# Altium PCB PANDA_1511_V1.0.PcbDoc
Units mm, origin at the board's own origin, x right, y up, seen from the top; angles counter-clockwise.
Board outline 50 x 34 mm, 2 copper layers (Top Layer, Bottom Layer); 45 components, 50 nets, 138 pads, 65 vias.
Unrouted connection lines stored in the file: 1.
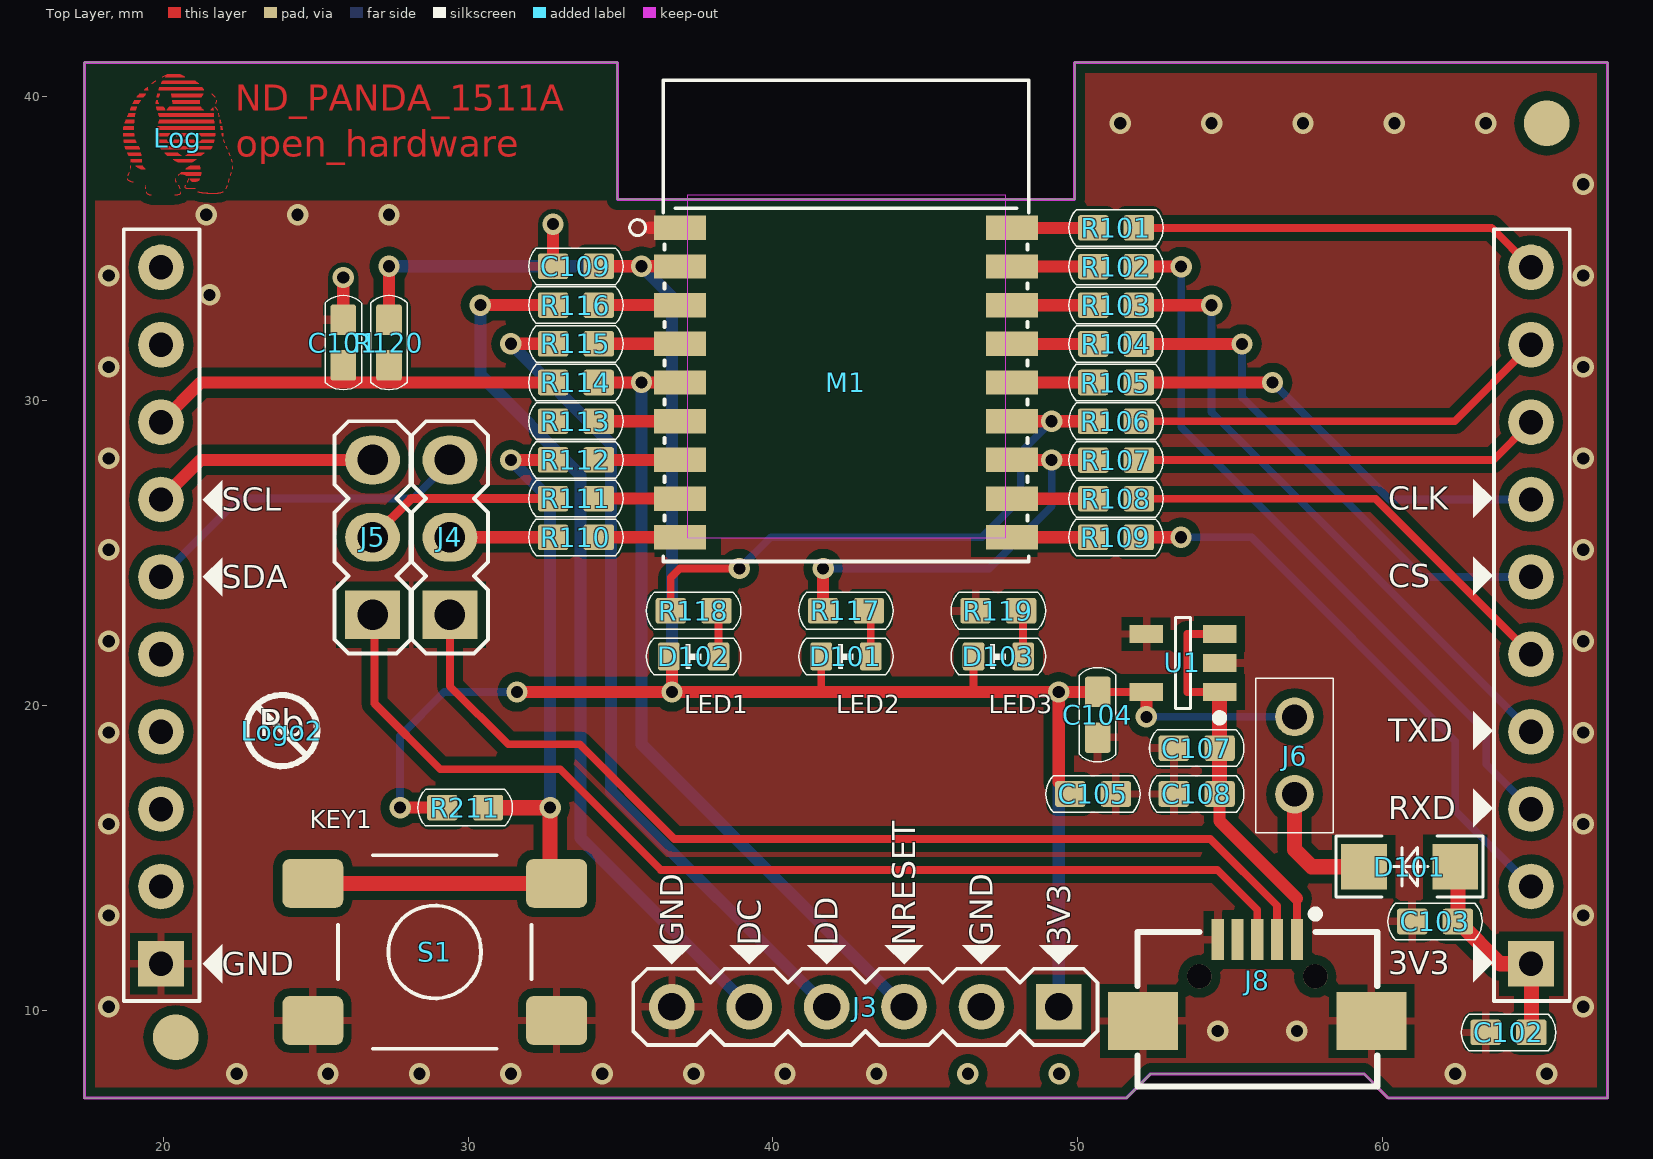
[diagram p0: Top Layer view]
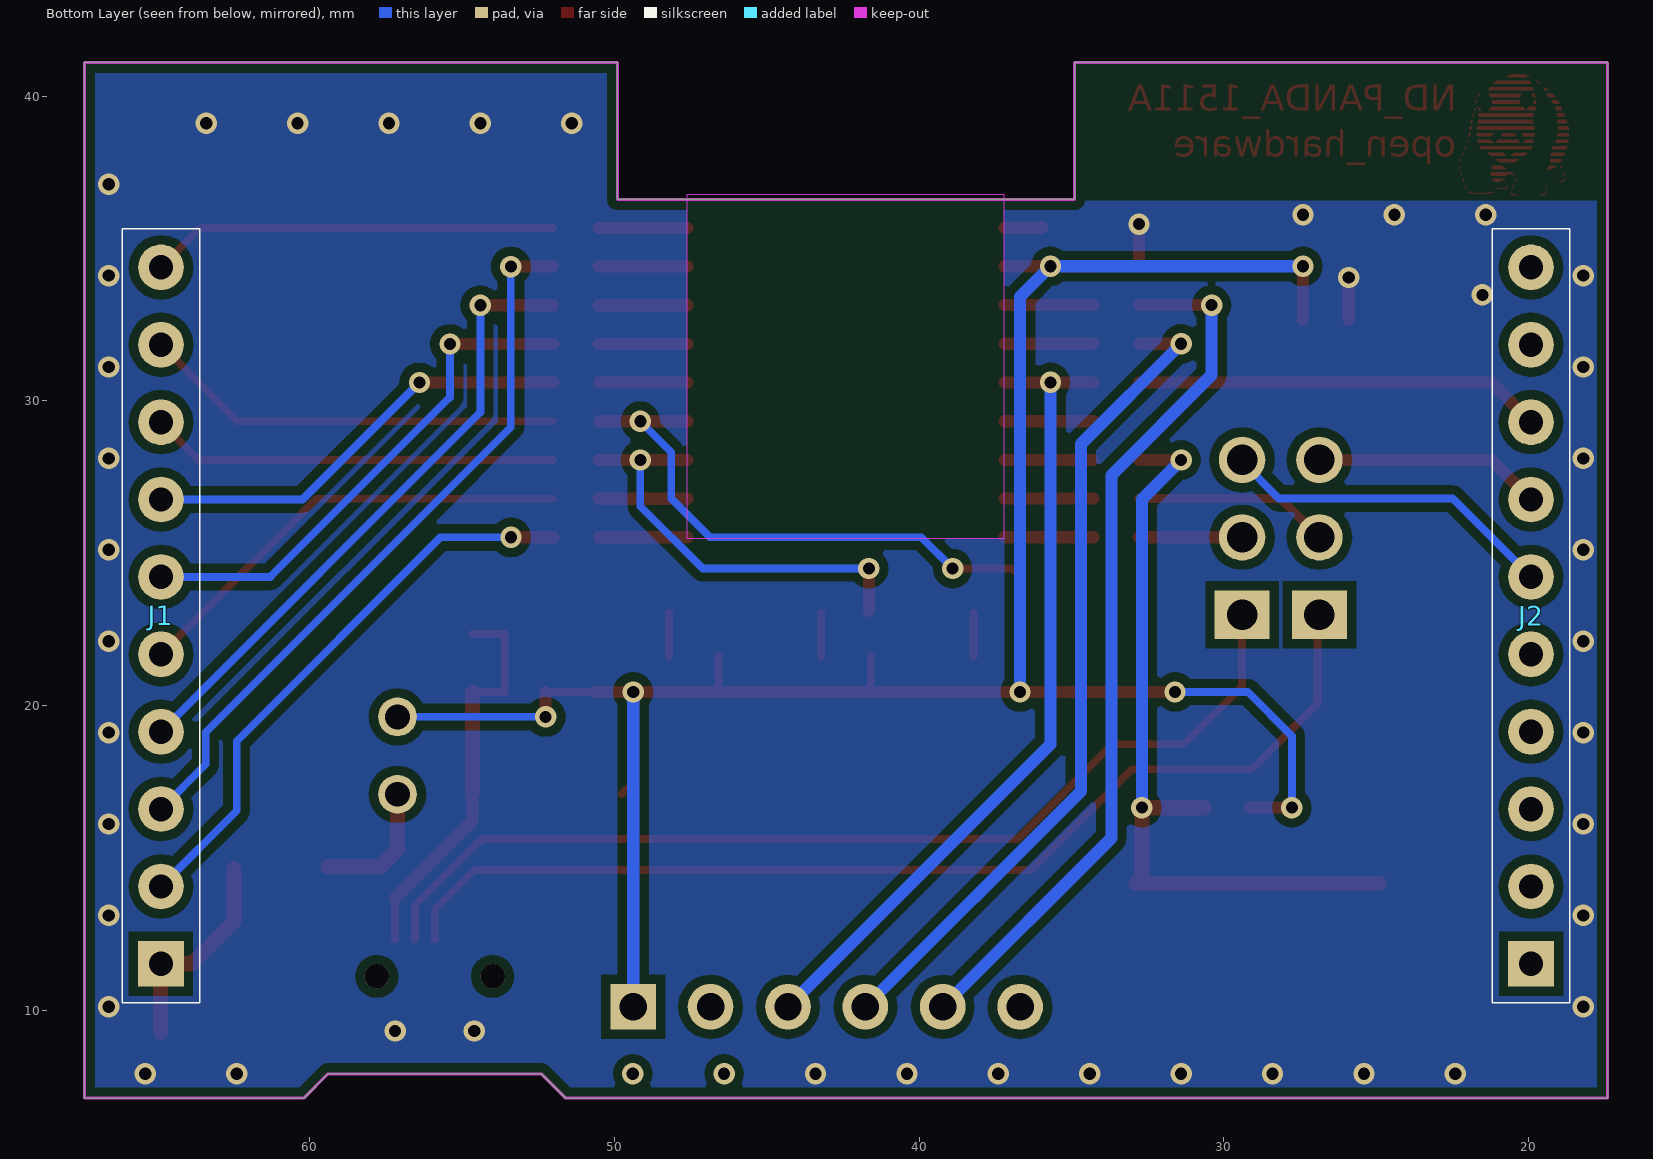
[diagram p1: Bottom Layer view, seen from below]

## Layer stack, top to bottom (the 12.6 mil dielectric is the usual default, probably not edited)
Top Solder: solder mask 0.0102, Solder Resist, Dk 3.5
Top Layer: signal copper 0.0356
Dielectric 1: dielectric 0.32, FR-4, Dk 4.8
Bottom Layer: signal copper 0.0356
Bottom Solder: solder mask 0.0102, Solder Resist, Dk 3.5

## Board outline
17.399,7.112 17.399,41.112 34.899,41.112 34.899,36.612 49.899,36.612 49.899,41.112 67.399,41.112 67.399,7.112 60.199,7.112 59.399,7.912 52.399,7.912 51.599,7.112

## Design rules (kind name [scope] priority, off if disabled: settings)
Clearance [All] p1: gap=0.3
ComponentClearance [All] p1 off: gap=0.254 collisioncheckmode=3 verticalgap=0.254 showdistances=FALSE
Height [All] p1 off: minheight=0 maxheight=25.4 prefheight=12.7
PolygonConnect [All] p1: connectstyle=Relief reliefconductorwidth=0.254 reliefentries=4 polygonreliefangle="90 Angle" airgapwidth=0.254
RoutingVias [All] p1: holewidth=0.711 width=1.27 viastyle="Through Hole" minholewidth=0.711 minwidth=1.27 maxholewidth=0.711 maxwidth=1.27
SilkToBoardRegionClearance [All] p1 off:
SolderMaskExpansion [All] p1: expansion=0.102
Width [All] p1: maxlimit=0.254 minlimit=0.254 preferedwidth=0.254
27 further rules are at their usual default settings.

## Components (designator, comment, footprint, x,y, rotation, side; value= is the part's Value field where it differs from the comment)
C101 "0.1uF" CAP_SMD_0603 25.899,32.547 r270 top
C102 "1uF" CAP_SMD_0603 63.512,9.271 r0 top
C103 "0.1uF" CAP_SMD_0603 61.099,12.912 r0 top
C104 "0.1uF" CAP_SMD_0603 50.659,19.062 r90 top
C105 "0.1uF" CAP_SMD_0603 51.143,17.097 r180 top
C107 "0.1uF" CAP_SMD_0603 53.274,18.601 r0 top
C108 "0.1uF" CAP_SMD_0603 53.274,17.097 r0 top
C109 "0.1uF" CAP_SMD_0603 32.899,34.417 r0 top
D101 "LED" LED_0603_RED 42.399,21.612 r0 top
D101 "Diode" LL34 60.899,14.712 r270 top
D102 "LED" LED_0603_BLUE 37.399,21.612 r0 top
D103 "LED" LED_0603_GREEN 47.399,21.612 r0 top
J1 "HDR1x10_2.54" HDR2R54_180_1X10F 64.884,22.952 r0 bottom locked
J2 "HDR1x10_2.54" HDR2R54_180_1X10F 19.914,22.952 r0 bottom locked
J3 "CON6" HDR2R54_180_1X6M 43.034,10.112 r270 top
J4 "CON3" HDR_2R54_180M_1X3DP 26.859,25.522 r90 top
J5 "CON3" HDR_2R54_180M_1X3DP 24.319,25.522 r90 top
J6 "CON2" HDR2R54_180_1X2M 57.121,18.358 r180 top
J8 "USB_M" USB_Micro 55.899,12.319 r0 top
Log "Necdaz_Panda" NECDAZ_PANDA 20.467,38.612 r0 top
Logo2 "Pb-Free Symbol" Pb-Free_Overlay_Small 23.876,19.177 r0 top
M1 "CC2541-BM-S02" [18]BM-S02 42.399,25.022 r90 top
R101 "1k" RES_SMD_0603 51.264,35.677 r0 top
R102 "1k" RES_SMD_0603 51.264,34.407 r0 top
R103 "1k" RES_SMD_0603 51.264,33.137 r0 top
R104 "1k" RES_SMD_0603 51.264,31.867 r0 top
R105 "1k" RES_SMD_0603 51.259,30.602 r0 top
R106 "1k" RES_SMD_0603 51.259,29.332 r0 top
R107 "1k" RES_SMD_0603 51.264,28.057 r0 top
R108 "1k" RES_SMD_0603 51.264,26.787 r0 top
R109 "1k" RES_SMD_0603 51.259,25.522 r0 top
R110 "1k" RES_SMD_0603 33.534,25.522 r180 top
R111 "1k" RES_SMD_0603 33.534,26.792 r180 top
R112 "1k" RES_SMD_0603 33.534,28.062 r180 top
R113 "1k" RES_SMD_0603 33.534,29.332 r0 top
R114 "1k" RES_SMD_0603 33.534,30.602 r0 top
R115 "1k" RES_SMD_0603 33.534,31.872 r180 top
R116 "1k" RES_SMD_0603 33.534,33.142 r180 top
R117 "20k" RES_SMD_0603 42.399,23.112 r180 top
R118 "20k" RES_SMD_0603 37.399,23.112 r180 top
R119 "20k" RES_SMD_0603 47.399,23.112 r180 top
R120 "20k" RES_SMD_0603 27.399,31.912 r90 top
R211 "20k" RES_SMD_0603 29.899,16.649 r180 top
S1 "SWITCH" SW_PB4_B1 28.899,11.912 r180 top
U1 "TPS709XXDBV" SOT23-5A 53.459,21.397 r180 top

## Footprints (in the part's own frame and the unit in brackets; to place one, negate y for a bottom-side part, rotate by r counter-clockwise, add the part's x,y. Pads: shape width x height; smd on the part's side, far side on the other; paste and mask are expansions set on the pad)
[18]BM-S02 [mm]
  rect 0.8x1.7 smd: 1(10.66,5.45) 2(9.39,5.45) 3(8.12,5.45) 4(6.85,5.45) 5(5.58,5.45) 6(4.31,5.45) 7(3.04,5.45) 8(1.77,5.45) 9(0.5,5.45) 10(0.5,-5.45) 11(1.77,-5.45) 12(3.04,-5.45) 13(4.31,-5.45) 14(5.58,-5.45) 15(6.85,-5.45) 16(8.12,-5.45) 17(9.39,-5.45) 18(10.66,-5.45)
  silkscreen extent -0.3,-6 15.5,6, body extent 0,-5.7 15.17,5.59, height 1.28
CAP_SMD_0603 [mm]
  rrect20% 1x0.84 smd: 1(-0.115,0) 2(1.385,0)
  silkscreen extent -0.91,-0.6 2.18,0.6, body extent -0.09,-0.38 1.51,0.42, height 0.3
HDR2R54_180_1X2M [mil]
  round 50 hole 32: 1(0,50) 2(0,-50)
  silkscreen extent -50,-100 50,100, body extent -49,-100 49,100, height 323
HDR2R54_180_1X6M [mm]
  rect 1.5x1.5 hole 0.9: 1(0,6.35)
  round 1.5 hole 0.9: 2(0,3.81) 3(0,1.27) 4(0,-1.27) 5(0,-3.81) 6(0,-6.35)
  silkscreen extent -1.25,-7.62 1.25,7.62, body extent -1.23,-7.62 1.27,7.62, height 8.2
HDR2R54_180_1X10F [mm]
  rect 1.5x1.5 hole 0.8: 1(0,11.43)
  round 1.5 hole 0.8: 2(0,8.89) 3(0,6.35) 4(0,3.81) 5(0,1.27) 6(0,-1.27) 7(0,-3.81) 8(0,-6.35) 9(0,-8.89) 10(0,-11.43)
  silkscreen extent -1.27,-12.7 1.27,12.7, body extent -1.25,-12.82 1.25,12.83, height 8.5
HDR_2R54_180M_1X3DP [mm]
  rect 1.6x1.8 hole 1: 1(-2.54,-2.54)
  oval 1.6x1.8 / inner round 1.524 / far side round 1.524 hole 1: 2(0,-2.54) 3(2.54,-2.54)
  silkscreen extent -3.81,-3.79 3.81,-1.29, body extent -3.81,-3.81 3.81,-1.27, height 10.2
LED_0603_BLUE [mil]
  rrect20% 28x36 smd: 1(-32,0) 2(32,0)
  silkscreen extent -61,-24 61,24, body extent -32,-16 32,16, height 24
LED_0603_GREEN [mil]
  rrect20% 28x36 smd: 1(-32,0) 2(32,0)
  silkscreen extent -61,-24 61,24, body extent -32,-16 32,16, height 24
LED_0603_RED [mil]
  rrect20% 28x36 smd: 1(-32,0) 2(32,0)
  silkscreen extent -61,-24 61,24, body extent -32,-16 32,16, height 24
LL34 [mm]
  rect 1.5x1.5 smd: 1(0,1.5) 2(0,-1.5)
  silkscreen extent -1,-2.41 1,2.41, body extent -0.73,-1.75 0.72,1.75, height 1.43
NECDAZ_PANDA [mm]
  Top Layer drawing of 7063 lines, arcs and shapes, not listed
Pb-Free_Overlay_Small [mm]
  silkscreen extent -1.16,-1.17 1.17,1.17
RES_SMD_0603 [mm]
  rrect20% 1x0.84 smd: 1(-0.75,0) 2(0.75,0)
  silkscreen extent -1.55,-0.6 1.55,0.6, body extent -0.8,-0.4 0.8,0.4, height 0.5
SOT23-5A [mm] "Max4173"
  rect 1.1x0.6 smd: 1(-1.2,0.95) 2(-1.2,0) 3(-1.2,-0.95) 4(1.2,-0.95) 5(1.2,0.95)
  silkscreen extent -1.33,-1.5 0.25,1.92, body extent -1.48,-1.5 1.52,1.5, height 1.3
SW_PB4_B1 [mm]
  rrect30% 2x1.6 smd: 1(-4,2.25) 2(-4,-2.25) 3(4,-2.25) 4(4,2.25)
  silkscreen extent -3.17,-3.18 3.17,3.18, body extent -4,-3 4,3, height 4.3
USB_Micro [mm]
  rect 0.4x1.35 smd: 1(1.3,0) 2(0.65,0) 3(0,0) 4(-0.65,0) 5(-1.3,0)
  rect 2.3x1.9 smd: 6(-3.75,-2.675) 7(3.75,-2.675)
  round 0.8 hole 0.8 unplated: MH1(1.9,-1.208) MH2(-1.9,-1.208)
  silkscreen extent -3.94,-4.82 3.94,0.96, body extent -3.99,-5.19 3.99,0.24, height 2.77

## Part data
C101 C102 C103 C104 C105 C107 C108 C109: library part CAP
J1 J2: "Header"
J3 J4 J5 J6: "Connector"
J8: "MicroUSB接口"
Logo2: library part Pb-Free
R101 R102 R103 R104 R105 R106 R107 R108 R109 R110 R111 R112 R113 R114 R115 R116 R117 R118 R119 R120 R211: library part RES2, "Resistor"

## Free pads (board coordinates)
  round 1.5 smd: 3(20.399,9.112) 3(65.399,39.112)

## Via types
v1: diameter 0.7, hole 0.4, Top Layer to Bottom Layer, 65 vias

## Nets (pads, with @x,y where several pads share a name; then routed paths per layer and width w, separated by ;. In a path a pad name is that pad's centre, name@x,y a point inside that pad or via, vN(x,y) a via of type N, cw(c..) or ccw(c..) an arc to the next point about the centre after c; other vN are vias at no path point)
3.3V: C104.2 C105.2 C109.2 D101.1@41.586,21.612 D102.1 D103.1 J3.1 J3.2 J6.2 M1.2 R120.2 R211.2 U1.5 | length 79
  Top Layer w0.254: 41.586,20.517 D101.1@41.586,21.612 ; 46.586,20.47 D103.1 ; C105.2@49.384,17.471 C105.2 ; C104.2 U1.5
  Top Layer w0.4: R120.2 v1(27.399,34.417) ; v1(27.764,16.649) R211.2 ; v1(31.599,20.447) v1(49.384,20.447) ; C109.2 v1(35.687,34.417) M1.2@37.194,34.417 ; v1(36.687,20.447) D102.1@36.687,21.511 ; C105.2@49.384,17.471 v1(49.384,20.447) ; C104.2 v1(49.384,20.447) ; v1(52.259,19.628) U1.5
  Bottom Layer w0.254: v1(27.764,16.649) 27.764,19.001 29.21,20.447 v1(31.599,20.447) ; v1(52.259,19.628) J6.2
  Bottom Layer w0.4: v1(27.399,34.417) v1(35.687,34.417) 36.687,33.417 v1(36.687,20.447) ; J3.1 v1(49.384,20.447)
DC: J3.4 R115.2 | length 27.4
  Top Layer w0.4: v1(31.399,31.872) R115.2
  Bottom Layer w0.4: v1(31.399,31.872) 34.687,28.584 34.687,17.189 J3.4
DD: J3.5 R116.2 | length 29.1
  Top Layer w0.4: v1(30.399,33.142) R116.2
  Bottom Layer w0.4: v1(30.399,33.142) 30.399,30.847 33.687,27.559 33.687,15.649 J3.5
GND: C101.1 C102.1 C103.1 C104.1 C105.1 C107.1 C108.1 C109.1 J2.1 J3.6 J8.5 J8.6 J8.7 M1.1 R119.2 S1.1 S1.4 U1.2 U1.4 | length 4
  Top Layer w0.4: C101.1 v1(25.899,34.047) ; C109.1 v1(32.784,35.802) ; 35.946,35.682 M1.1@37.199,35.682
  other v1: 22.399,7.912 25.399,7.912 28.399,7.912 31.399,7.912 34.399,7.912 37.399,7.912 40.399,7.912 43.399,7.912 62.399,7.912 65.399,7.912 54.599,9.319 57.199,9.319 18.199,10.112 66.599,10.112 18.199,13.112 66.599,13.112 18.199,16.112 66.599,16.112 18.199,19.112 66.599,19.112 18.199,22.112 66.599,22.112 18.199,25.112 66.599,25.112 18.199,28.112 66.599,28.112 18.199,31.112 66.599,31.112 21.511,33.48 18.199,34.112 66.599,34.112 21.399,36.112 24.399,36.112 27.399,36.112 66.599,37.112 51.399,39.112 54.399,39.112 57.399,39.112 60.399,39.112 63.399,39.112
MP1.0: J1.2 R109.2 | length 19
  Top Layer w0.4: R109.2 v1(53.394,25.522)
  Bottom Layer w0.254: v1(53.394,25.522) 55.71,25.522 62.4,18.832 62.4,16.546 J1.2
MP1.3: J1.5 R108.2 | length 15
  Top Layer w0.254: R108.2 59.779,26.787 J1.5
MP1.4: J1.6 R104.2 | length 17.1
  Top Layer w0.4: R104.2 v1(55.399,31.867)
  Bottom Layer w0.254: v1(55.399,31.867) 55.399,30.115 61.292,24.222 J1.6
MP1.5: J1.7 R105.2 | length 14.5
  Top Layer w0.4: R105.2 v1(56.399,30.602)
  Bottom Layer w0.254: v1(56.399,30.602) 60.239,26.762 J1.7
MP2.0: J1.8 R107.2 | length 13.4
  Top Layer w0.254: R107.2 63.639,28.057 J1.8
MP2.1: J1.9 R106.2 | length 13.9
  Top Layer w0.254: R106.2 62.374,29.332 J1.9
MP2.2: J1.10 R101.2 | length 13.4
  Top Layer w0.254: R101.2 63.589,35.677 J1.10
MP2.3: J2.10
MP2.4: J2.9
MP2.5: C101.2 J2.8 R114.1 R120.1 | length 13.4
  Top Layer w0.4: J2.8 21.214,30.602 R114.1
MP2.6: J2.2
MP2.7: J2.3
MRXD: J1.3 R102.2 | length 23.9
  Top Layer w0.4: R102.2 v1(53.399,34.407)
  Bottom Layer w0.254: v1(53.399,34.407) 53.399,29.14 63.416,19.123 63.416,18.07 J1.3
MTXD: J1.4 R103.2 | length 20.7
  Top Layer w0.4: R103.2 v1(54.399,33.137)
  Bottom Layer w0.254: v1(54.399,33.137) 54.399,29.627 J1.4
NetC102_2: C102.2 C103.2 D101.1@62.399,14.712 J1.1 | length 7
  Top Layer w0.254: D101.1@62.399,14.712 D101.1@62.484,14.627
  Top Layer w0.5: D101.1@62.484,14.627 C103.2 63.874,11.522 J1.1 ; C102.2 J1.1@64.897,11.509
NetD101_2: D101.2@43.212,21.612 R117.1 | length 1.4
  Top Layer w0.254: D101.2@43.212,21.612 R117.1@43.212,23.049
NetD102_2: D102.2 R118.1 | length 1.4
  Top Layer w0.254: D102.2 R118.1@38.212,23.049
NetD103_2: D103.2 R119.1 | length 1.4
  Top Layer w0.254: D103.2 R119.1@48.212,23.049
NetM1_6: M1.6 R113.2 | length 2.9
  Top Layer w0.4: R113.2 M1.6@37.199,29.332
NetM1_7: M1.7 R112.1 | length 2.9
  Top Layer w0.4: R112.1 M1.7@37.199,28.062
NetM1_8: M1.8 R111.1 | length 2.9
  Top Layer w0.4: R111.1 M1.8@37.199,26.792
NetM1_9: M1.9 R110.1 | length 2.9
  Top Layer w0.4: R110.1 M1.9@37.199,25.522
NRESET: J3.3 M1.5 R114.2 | length 27
  Top Layer w0.4: R114.2 M1.5@37.199,30.602
  Bottom Layer w0.4: v1(35.687,30.607) 35.687,18.729 J3.3
P0.1: M1.18 R101.1 | length 2.9
  Top Layer w0.4: M1.18@47.604,35.677 R101.1
P0.4: M1.15 R104.1 | length 2.9
  Top Layer w0.4: M1.15@47.604,31.867 R104.1
P0.5: M1.14 R105.1 | length 2.9
  Top Layer w0.4: M1.14@47.599,30.602 R105.1
P0.6: M1.13 R106.1 R118.2 | length 19.5
  Top Layer w0.254: R118.2 36.649,24.203 36.943,24.497 v1(38.899,24.497)
  Top Layer w0.4: M1.13@47.599,29.332 v1(49.149,29.332) R106.1
  Bottom Layer w0.254: v1(38.899,24.497) 39.929,25.527 46.863,25.527 48.133,26.797 48.133,28.316 v1(49.149,29.332)
P0.7: M1.12 R107.1 R117.2 | length 14.2
  Top Layer w0.4: R117.2 v1(41.649,24.497) ; M1.12@47.604,28.057 v1(49.149,28.057) R107.1
  Bottom Layer w0.254: v1(41.649,24.497) 47.103,24.497 49.149,26.543 v1(49.149,28.057)
P1.1: M1.11 R108.1 | length 2.9
  Top Layer w0.4: M1.11@47.604,26.787 R108.1
P1.2: M1.10 R109.1 | length 2.9
  Top Layer w0.4: M1.10@47.599,25.522 R109.1
P1.7: R112.2 R211.1 S1.2 S1.3 | length 25.9
  Top Layer w0.254: S1.2@32.687,14.374 S1.2
  Top Layer w0.4: v1(31.399,28.062) R112.2
  Top Layer w0.5: S1.3 S1.2 ; R211.1 v1(32.687,16.649) S1.2@32.687,14.374
  Bottom Layer w0.4: v1(31.399,28.062) 32.687,26.774 v1(32.687,16.649)
P2.0: R113.1
P2.1: M1.3 R116.1 | length 2.9
  Top Layer w0.4: R116.1 M1.3@37.199,33.142
P2.2: M1.4 R115.1 | length 2.9
  Top Layer w0.4: R115.1 M1.4@37.199,31.872
RESET: J2.5
RX: M1.16 R103.1 | length 2.9
  Top Layer w0.4: M1.16@47.604,33.137 R103.1
SCL: J2.7 J5.3 | length 7.5
  Top Layer w0.4: J2.7 21.214,28.062 J5.3
SCL/U+: J5.2 R111.2 | length 6.5
  Top Layer w0.3: J5.2 28.129,26.792 R111.2
SDA: J2.6 J4.3 | length 11.1
  Bottom Layer w0.254: J2.6 22.489,26.797 28.194,26.797 J4.3@29.464,28.067
SDA/U-: J4.2 R110.2 | length 3.4
  Top Layer w0.4: J4.2 R110.2
TEST: J2.4
TX: M1.17 R102.1 | length 2.9
  Top Layer w0.4: M1.17@47.604,34.407 R102.1
U+: J5.1 J8.3 | length 35.7
  Top Layer w0.254: J5.1@26.924,22.987 26.924,20.066 29.083,17.907 33.02,17.907 36.322,14.605 54.589,14.605 55.899,13.295 J8.3
U-: J4.1 J8.2 | length 33.6
  Top Layer w0.254: J4.1 29.399,20.639 31.312,18.726 33.655,18.726 36.76,15.621 54.356,15.621 56.549,13.428 J8.2
USB_VDD: C107.2 C108.2 J8.1 U1.1 U1.3 | length 13.2
  Top Layer w0.254: 53.599,20.442 53.599,22.347 U1.3 ; 53.604,20.447 U1.1 ; J8.1 57.199,13.667
  Top Layer w0.4: C108.2 54.659,16.207 57.199,13.667
  Top Layer w0.5: C108.2 C107.2 U1.1
VIN: D101.2@59.399,14.712 J6.1 | length 4.3
  Top Layer w0.5: J6.1 57.121,15.269 57.678,14.712 D101.2@59.399,14.712
pads on no net: J8.4 J8.MH1 J8.MH2
copper on no net:
  other v1: 46.399,7.912 49.399,7.912

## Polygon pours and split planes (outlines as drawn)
GND on Top Layer "Top Layer-No Net" (solid, pour order 0): 17.399,7.112 17.399,36.576 49.863,36.576 49.899,36.612 49.899,41.112 67.399,41.112 67.399,7.112 60.199,7.112 59.399,7.912 52.399,7.912 51.599,7.112 17.399,7.112
no net on Bottom Layer "Top Layer-No Net" (solid, pour order 2): 17.399,7.112 17.399,36.576 49.863,36.576 49.899,36.612 49.899,41.112 67.399,41.112 67.399,7.112 60.199,7.112 59.399,7.912 52.399,7.912 51.599,7.112 17.399,7.112

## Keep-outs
Keep-Out Layer:
  pour cut-out: 37.199,25.492 37.199,36.772 47.625,36.772 47.625,25.492
  lines w0.1: 17.399,7.112 17.399,41.112 34.899,41.112 34.899,36.612 49.899,36.612 49.899,41.112 67.399,41.112 67.399,7.112 60.199,7.112 59.399,7.912 52.399,7.912 51.599,7.112 29.899,7.112 17.399,7.112

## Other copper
Top Layer:
  text "ND_PANDA_1511A" at 22.352,39.243 h1.45

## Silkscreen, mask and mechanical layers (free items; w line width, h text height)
Top Overlay:
  circle w0.1: c35.56,35.687 r0.262
  region: 62.992,26.162 63.627,26.797 62.992,27.432
  region: 21.922,26.127 21.287,26.762 21.922,27.397
  region: 21.922,23.587 21.287,24.222 21.922,24.857
  region: 62.992,23.622 63.627,24.257 62.992,24.892
  region: 62.992,18.542 63.627,19.177 62.992,19.812
  region: 62.992,16.002 63.627,16.637 62.992,17.272
  region: 62.992,10.922 63.627,11.557 62.992,12.192
  region: 21.922,10.887 21.287,11.522 21.922,12.157
  region: 37.319,12.136 36.684,11.501 36.049,12.136
  region: 39.859,12.136 39.224,11.501 38.589,12.136
  region: 42.399,12.136 41.764,11.501 41.129,12.136
  region: 44.939,12.136 44.304,11.501 43.669,12.136
  region: 47.479,12.136 46.844,11.501 46.209,12.136
  region: 50.019,12.136 49.384,11.501 48.749,12.136
  lines w0.127: 18.694,35.622 18.694,10.302 21.184,10.302 21.184,35.632 18.704,35.632 ; 63.664,35.622 63.664,10.302 66.154,10.302 66.154,35.632 63.674,35.632
  text "CLK" at 60.198,26.162 h1.3
  text "SCL" at 21.91,26.127 h1.3
  text "CS" at 60.198,23.622 h1.3
  text "SDA" at 21.91,23.587 h1.3
  text "LED1" at 37.084,19.558 h1
  text "LED2" at 42.084,19.558 h1
  text "LED3" at 47.084,19.558 h1
  text "TXD" at 60.198,18.542 h1.3
  text "RXD" at 60.198,16.002 h1.3
  text "KEY1" at 24.797,15.776 h1
  text "GND" at 37.319,12.124 h1.3 r90
  text "DC" at 39.859,12.124 h1.3 r90
  text "DD" at 42.399,12.124 h1.3 r90
  text "NRESET" at 44.939,12.124 h1.3 r90
  text "GND" at 47.479,12.124 h1.3 r90
  text "3V3" at 50.019,12.124 h1.3 r90
  text "3V3" at 60.198,10.922 h1.3
  text "GND" at 21.91,10.887 h1.3
Top Solder:
  rectangle: 17.399,36.568 34.899,41.112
